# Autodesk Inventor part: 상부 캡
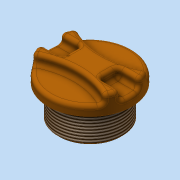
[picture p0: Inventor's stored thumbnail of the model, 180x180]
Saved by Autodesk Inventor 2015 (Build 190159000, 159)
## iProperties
Created: 2016-09
Part Number: 상부 캡
Material: ABS 플라스틱
Document SubType Name: Modeling
Designer: mduedu
Density: 1.06 g/cm^3
Appearance: 주황색
Mass: 23.2119 g
Surface Area: 67.9046 cm^2
Volume: 21.898 cm^3
Author: mduedu
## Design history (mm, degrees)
sketch "스케치1"
  geometry: C1 r 22.5 at (0, 0); 1 further point
  constraints: 1 centre point, 1 coincident
  dimensions: "d0" = 45 diameter of C1
extrude "돌출1" new body sketch "스케치1" distance "d1" = 10; taper "d2" = 0 deg
sketch "스케치2" dims "d4" = 80
  geometry: C1 r 22.5 at (0, 0) reference; 3 further points
  constraints: 3 vertical alignment, 2 other
  dimensions: "d3" = 7 distance of point (0, 7) point (0, 0)
extrude "돌출2" cut sketch "스케치2" distance "d5" = 5; taper "d6" = 0 deg
sketch "스케치3"
  geometry: L1 (-22.5, 0)-(0, 0); L2 (-21.937, 5)-(-10, 5); L3 (-10, 5)-(-10, -5); L4 (-10, -5)-(-21.937, -5); A1 r 22.5 centre (0, 0) between (-19.118, 11.864) and (-19.118, -11.864) reference; A2 r 22.5 centre (0, 0) between (-21.937, 5) and (-21.937, -5); 1 further point
  constraints: 8 end point, 5 point on circle, 2 horizontal, 1 centre point, 1 coincident, 1 parallel, 1 perpendicular, 1 symmetric about line
  dimensions: "d7" = 10 distance from line of L3 point (0, 0); "d8" = 10 distance of L2.end L3.end
extrude "돌출3" cut sketch "스케치3" distance "d9" = 5; taper "d10" = 0 deg
fillet "모깎기1" dims "d11" = 2
fillet "모깎기2" dims "d12" = 2
fillet "모깎기3" dims "d13" = 2
sketch "스케치4"
  geometry: C1 r 17.5 at (0, 0); 1 further point
  constraints: 1 centre point, 1 coincident
  dimensions: "d14" = 35 diameter of C1
extrude "돌출4" join sketch "스케치4" distance "d15" = 17; taper "d16" = 0 deg
sketch "스케치5"
  geometry: C1 r 12.5 at (0, 0); 1 further point
  constraints: 1 centre point, 1 coincident
  dimensions: "d17" = 25 diameter of C1
extrude "돌출5" cut sketch "스케치5" distance "d18" = 10; taper "d19" = 0 deg
fillet "모깎기4" dims "d20" = 3
feature "스레드1" dims "d21" = 10, "d22" = 0
chamfer "모따기1" distance "d23" = 1; stored, may be unused: second distance "d24" = 2, angle "d25" = 45 deg
node "솔리드1"
mirror "대칭1"
mirror "대칭2"
node "투영된 루프1"
